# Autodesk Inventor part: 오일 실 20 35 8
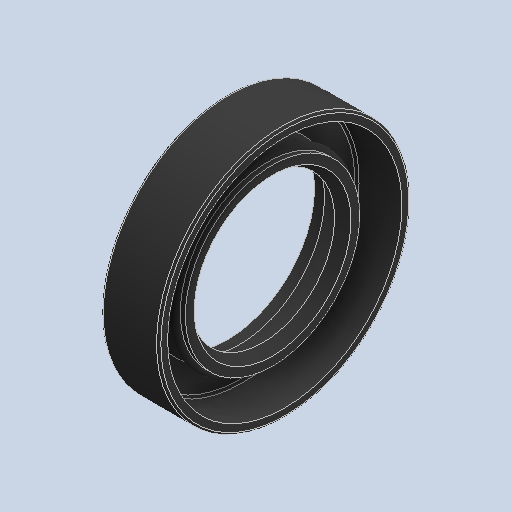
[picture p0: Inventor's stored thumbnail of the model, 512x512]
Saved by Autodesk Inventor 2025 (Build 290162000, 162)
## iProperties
Created: 2026-01
Part Number: 오일 실 20 35 8
Material: 고무
Description: 오일-실
Document SubType Name: Modeling
Designer: KDI
Density: 0.93 g/cm^3
Appearance: 기본값
Author: jhkim
Sending System: Autodesk Inventor 2026
Preprocessor: ST-DEVELOPER v20.1
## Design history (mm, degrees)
feature "Solid1"
node "솔리드1"
